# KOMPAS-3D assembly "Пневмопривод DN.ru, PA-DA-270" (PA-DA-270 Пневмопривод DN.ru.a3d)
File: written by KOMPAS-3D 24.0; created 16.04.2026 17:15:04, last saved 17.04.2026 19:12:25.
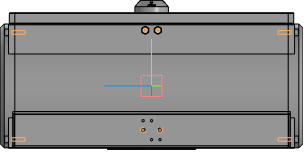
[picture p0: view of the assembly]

Document properties: Автор: DN.ru; Полное имя файла: C:\Работа\PA-DA-х Пневмопривод DN.ru\270\исходные материалы\PA-DA-270 Пневмопривод DN.ru.a3d

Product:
- Component [detail]: Пневмопривод DN.ru  | designation PA-DA-270  | qty 1  | pos. 1  | Масса: 97; Раздел спецификации: Прочие изделия; Примечание: D290-00301; Автор: DN.ru; source file: PA-DA-270 Пневмопривод DN.ru.m3d
- Component [standard]: Болт М10-6gx50 ГОСТ 7805-70  | qty 1  | pos. 2  | Масса: 0.04195; Раздел спецификации: Стандартные изделия; Рассекать на разрезах: no
- Component [standard]: Болт М10-6gx50 ГОСТ 7805-70  | qty 1  | Масса: 0.04195; Раздел спецификации: Стандартные изделия; Рассекать на разрезах: no
- Component [standard]: Гайка М10-6H ГОСТ 5915-70  | qty 1  | pos. 3  | Масса: 0.01206; Раздел спецификации: Стандартные изделия; Рассекать на разрезах: no
- Component [standard]: Гайка М10-6H ГОСТ 5915-70  | qty 1  | Масса: 0.01206; Раздел спецификации: Стандартные изделия; Рассекать на разрезах: no
- Component [standard]: Винт М10-6gx40 ГОСТ 11738-84  | qty 8  | pos. 4  | Масса: 0.03345; Раздел спецификации: Стандартные изделия; Рассекать на разрезах: no
- Part/product: Пневмопривод DN.ru  | designation PA-DA-270
    Масса: 97
    Раздел спецификации: Прочие изделия
    Примечание: D290-00301

Expressions: D290-00301
Referenced files in C:\Работа\PA-DA-х Пневмопривод DN.ru\270\исходные материалы\: PA-DA-270 Пневмопривод DN.ru.m3d
Referenced files in C:\Program Files\ASCON\KOMPAS-3D v24\Libs\PolynomLib\DATA\vault\Methods\Kompas\3D\: PLib_Screw_GOST_11738_1500.m3d, PLib_Bolt_1_900.m3d, PLib_Nut_OST92_900.m3d
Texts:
  PA-DA-270
  Крепежное изделие ГОСТ
  BOSimple***PART:f6352c65-8636-7196-6402-d592979e6031***SHORTLOC:Root±30±20±10±80±10±©{}30±©{BASE}130±30[Нет;Без покрытия;Без указания материала;50;10;17;1,5;-]
  BOSimple***PART:2c395b93-8c4a-cf39-bcf6-f45056cee6ca***SHORTLOC:Root±30±10±20±©{}110±10±50±60[Нет;Без покрытия;Без указания материала;-;10;1,5;17]
  BOSimple***PART:011d863b-f530-88e0-fdd6-78b6a69773f1***SHORTLOC:Root±30±20±10±80±10±GMC90[Нет;Без покрытия;Без указания материала;1,5;-;40;10]
  Программные изделия  и базы данных
  PA-DA-270 Пневмопривод DN.ru
  Болт М10-6gx50 ГОСТ 7805-70 (1)
  hole1
  hole2
  Болт М10-6gx50 ГОСТ 7805-70 (2)
  Гайка М10-6H ГОСТ 5915-70 (1)
  bcut1
  hcut1
  cut1
  Гайка М10-6H ГОСТ 5915-70 (2)
  Винт М10-6gx40 ГОСТ 11738-84 (1)
  Винт М10-6gx40 ГОСТ 11738-84 (2)
  Винт М10-6gx40 ГОСТ 11738-84 (3)
  Винт М10-6gx40 ГОСТ 11738-84 (4)
  Винт М10-6gx40 ГОСТ 11738-84 (5)
  Винт М10-6gx40 ГОСТ 11738-84 (6)
  Винт М10-6gx40 ГОСТ 11738-84 (7)
  Винт М10-6gx40 ГОСТ 11738-84 (8)
  Plane. Начало координат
